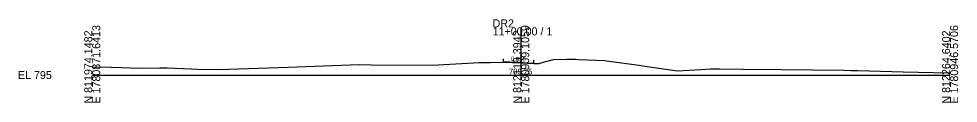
# Model space of a CAD drawing. Extents: x -26 to 303, y -10 to 2560.
# Drawn here: x -25.7 to 302.8, y 1490.3 to 1519.5 of the extents above; entities that cross this region are included whole.
import ezdxf

# ---------------------------------------------------------------- set-up
doc = ezdxf.new("R2010")
doc.units = 0
for name, color, linetype in [('Exist Cross Section Cell', 7, 'Continuous'), ('Exist XS Center Line Elevation Label', 7, 'Continuous'), ('Exist XS Ground Line', 7, 'Continuous'), ('Prop XS Dump Level', 7, 'Continuous'), ('Prop XS EOT Tick Mark', 7, 'Continuous'), ('Prop XS Finish Grade Pavement', 7, 'Continuous'), ('Prop XS SE Text', 7, 'Continuous')]:
    doc.layers.add(name, color=color, linetype=linetype)

msp = doc.modelspace()

# ---------------------------------------------------------------- linework, layer by layer
at = {"layer": 'Exist Cross Section Cell'}
for p, q in [((150, 1500), (150, 1516.68)), ((0, 1500), (150, 1500)), ((150, 1500), (300, 1500))]:
    msp.add_line(p, q, dxfattribs=at)
at = {"layer": 'Exist XS Ground Line'}
for p, q in [((158.21, 1504.65), (161.35, 1505.38)), ((161.35, 1505.38), (165.92, 1505.56)), ((165.92, 1505.56), (169, 1505.51)), ((169, 1505.51), (170.19, 1505.48)), ((170.19, 1505.48), (179.12, 1505.08)), ((179.12, 1505.08), (179.89, 1504.95)), ((179.89, 1504.95), (191.24, 1503.42)), ((0, 1502.81), (3.28, 1502.82)), ((3.28, 1502.82), (13.51, 1502.49)), ((13.51, 1502.49), (16.16, 1502.45)), ((16.16, 1502.45), (23.69, 1502.52)), ((23.69, 1502.52), (26.19, 1502.51)), ((26.19, 1502.51), (34.61, 1502.14)), ((34.61, 1502.14), (36.66, 1502.02)), ((36.66, 1502.02), (44.27, 1501.99)), ((44.27, 1501.99), (68.51, 1502.81)), ((68.51, 1502.81), (90.25, 1503.52)), ((90.25, 1503.52), (93.46, 1503.7)), ((93.46, 1503.7), (97.56, 1503.57)), ((97.56, 1503.57), (118.93, 1503.47)), ((118.93, 1503.47), (133.34, 1504.25)), ((133.34, 1504.25), (135.07, 1504.41)), ((135.07, 1504.41), (136.47, 1504.37)), ((136.47, 1504.37), (139.19, 1504.42)), ((139.19, 1504.42), (143.79, 1504.56)), ((143.79, 1504.56), (150, 1504.25)), ((150, 1504.25), (154.37, 1504.03)), ((154.37, 1504.03), (156.3, 1504.09)), ((156.3, 1504.09), (158.21, 1504.65)), ((191.24, 1503.42), (194.03, 1503.04)), ((194.03, 1503.04), (204.72, 1501.51)), ((204.72, 1501.51), (212.84, 1501.96)), ((212.84, 1501.96), (216.19, 1502.15)), ((216.19, 1502.15), (219.36, 1502.12)), ((219.36, 1502.12), (227.69, 1502.1)), ((227.69, 1502.1), (240.9, 1501.97)), ((240.9, 1501.97), (262.85, 1501.7)), ((262.85, 1501.7), (265.29, 1501.63)), ((265.29, 1501.63), (267.78, 1501.57)), ((267.78, 1501.57), (283.63, 1501.16)), ((283.63, 1501.16), (299.29, 1500.82)), ((299.29, 1500.82), (300, 1500.77))]:
    msp.add_line(p, q, dxfattribs=at)
at = {"layer": 'Prop XS Dump Level'}
for p, q in [((143.79, 1504.68), (150, 1504.38)), ((150, 1504.38), (154.37, 1504.16))]:
    msp.add_line(p, q, dxfattribs=at)
at = {"layer": 'Prop XS EOT Tick Mark'}
for p, q in [((143.79, 1504.68), (143.79, 1505.68)), ((154.37, 1504.16), (154.37, 1505.16))]:
    msp.add_line(p, q, dxfattribs=at)
at = {"layer": 'Prop XS Finish Grade Pavement'}
for p, q in [((143.79, 1504.68), (150, 1504.38)), ((150, 1504.38), (154.37, 1504.16))]:
    msp.add_line(p, q, dxfattribs=at)

# ---------------------------------------------------------------- texts
at = {"layer": 'Exist Cross Section Cell'}
for s, p in [('DR2', (140, 1516.68)), ('11+00.00 / 1', (140, 1513.88)), ('EL 795', (-26, 1498.6))]:
    msp.add_text(s, height=2.8, dxfattribs=at).set_placement(p)
for s, p in [('N 811974.1482', (0, 1490)), ('E 1780871.6413', (2.8, 1490)), ('N 812119.3942', (150, 1490)), ('E 1780909.1059', (152.8, 1490)), ('N 812264.6402', (300, 1490)), ('E 1780946.5706', (302.8, 1490))]:
    msp.add_text(s, height=2.8, rotation=90, dxfattribs=at).set_placement(p)
at = {"layer": 'Exist XS Center Line Elevation Label'}
msp.add_text('799.25', height=2, dxfattribs=at).set_placement((145.74, 1500.25))
at = {"layer": 'Prop XS SE Text'}
msp.add_text('0.050', height=1.5, rotation=357.1547, dxfattribs=at).set_placement((146.37, 1504.98))

doc.saveas('drawing.dxf')
